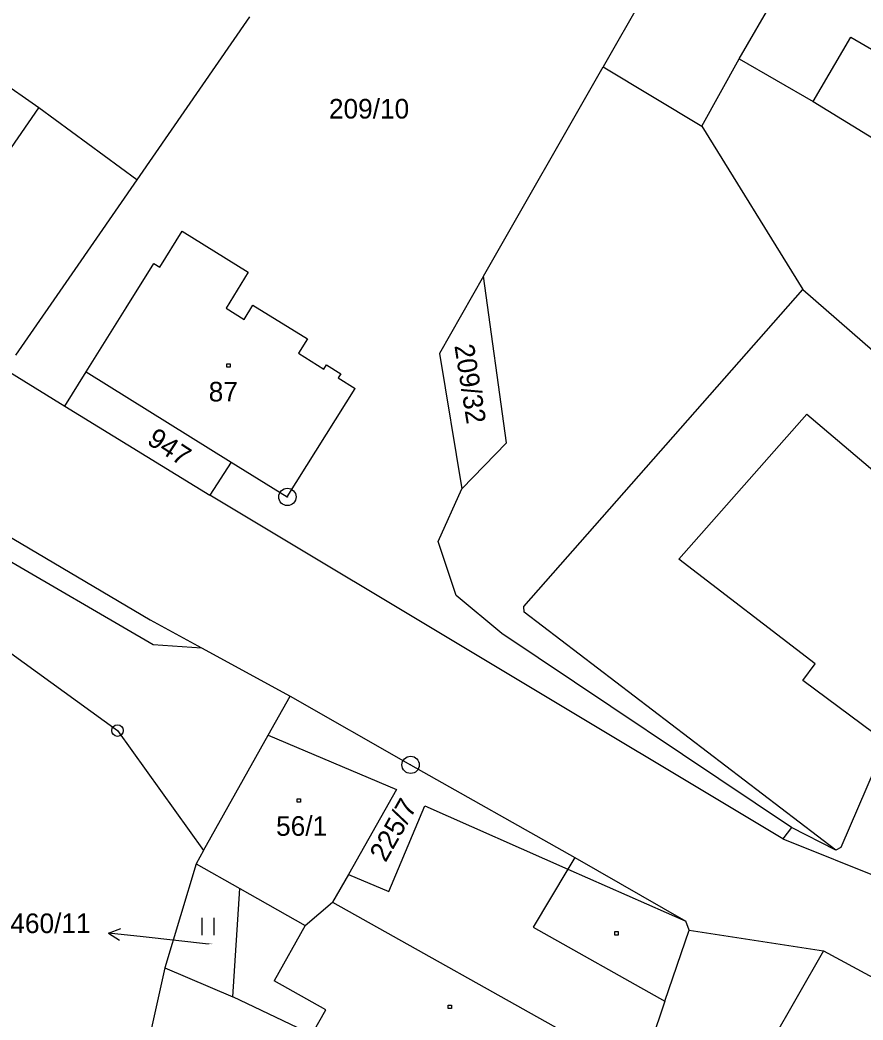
# Model space of a CAD drawing. Extents: x -796130 to -793145, y -1109506 to -1106267.
# Drawn here: x -794664.8 to -794591.8, y -1107676.5 to -1107589.9 of the extents above; entities that cross this region are included whole.
import ezdxf

# ---------------------------------------------------------------- set-up
doc = ezdxf.new("R2010")
doc.units = 0
for name, color, linetype in [('Komunikace', 7, 'Continuous'), ('Vrstva 1', 7, 'Continuous'), ('Vrstva 14', 7, 'Continuous'), ('Vrstva 15', 7, 'Continuous'), ('Vrstva 16', 7, 'Continuous'), ('Vrstva 2', 7, 'Continuous'), ('Vrstva 23', 7, 'Continuous'), ('Vrstva 25', 7, 'Continuous'), ('Vrstva 28', 7, 'Continuous')]:
    doc.layers.add(name, color=color, linetype=linetype)

msp = doc.modelspace()

# ---------------------------------------------------------------- linework, layer by layer
at = {"layer": 'Komunikace'}
msp.add_line((-794648.51, -1107669.95), (-794654.18, -1107669.32), dxfattribs=at)
at = {"layer": 'Vrstva 1'}
for p, q in [((-794605.66, -1107578.68), (-794614.29, -1107593.93)), ((-794644.96, -1107589.6), (-794654.73, -1107603.72)), ((-794624.67, -1107612.07), (-794614.29, -1107593.93)), ((-794614.29, -1107593.93), (-794605.74, -1107599.07)), ((-794605.74, -1107599.07), (-794602.51, -1107593.23)), ((-794602.51, -1107593.23), (-794596.1, -1107596.92)), ((-794596.1, -1107596.92), (-794590.11, -1107600.59)), ((-794667.79, -1107604.08), (-794663.22, -1107597.48)), ((-794654.73, -1107603.72), (-794663.22, -1107597.48)), ((-794605.74, -1107599.07), (-794596.99, -1107613.22)), ((-794654.73, -1107603.72), (-794660.1, -1107611.48)), ((-794652.74, -1107611.28), (-794650.79, -1107608.16)), ((-794650.79, -1107608.16), (-794645.06, -1107611.71)), ((-794655.65, -1107614.81), (-794653.25, -1107610.96)), ((-794653.25, -1107610.96), (-794652.74, -1107611.28)), ((-794660.1, -1107611.48), (-794665.24, -1107618.91)), ((-794645.06, -1107611.71), (-794646.98, -1107614.84)), ((-794624.67, -1107612.07), (-794628.49, -1107618.76)), ((-794622.69, -1107626.51), (-794624.67, -1107612.07)), ((-794596.99, -1107613.22), (-794570.24, -1107636.6)), ((-794645.43, -1107615.81), (-794644.66, -1107614.57)), ((-794644.66, -1107614.57), (-794639.94, -1107617.5)), ((-794659.11, -1107620.36), (-794655.65, -1107614.81)), ((-794646.98, -1107614.84), (-794645.43, -1107615.81)), ((-794639.94, -1107617.5), (-794640.71, -1107618.74)), ((-794640.71, -1107618.74), (-794638.51, -1107620.11)), ((-794628.49, -1107618.76), (-794626.55, -1107630.5)), ((-794638.51, -1107620.11), (-794638.28, -1107619.75)), ((-794638.28, -1107619.75), (-794637.05, -1107620.51)), ((-794666.1, -1107620.16), (-794660.96, -1107623.34)), ((-794660.96, -1107623.34), (-794659.11, -1107620.36)), ((-794659.11, -1107620.36), (-794646.53, -1107628.17)), ((-794637.05, -1107620.51), (-794637.28, -1107620.88)), ((-794637.28, -1107620.88), (-794635.79, -1107621.8)), ((-794641.68, -1107631.18), (-794635.79, -1107621.8)), ((-794660.96, -1107623.34), (-794648.39, -1107631.04)), ((-794626.55, -1107630.5), (-794622.69, -1107626.51)), ((-794646.53, -1107628.17), (-794648.39, -1107631.04)), ((-794646.53, -1107628.17), (-794641.68, -1107631.18)), ((-794673.06, -1107630.3), (-794653.57, -1107641.84)), ((-794598.74, -1107660.82), (-794648.39, -1107631.04)), ((-794628.61, -1107635.05), (-794626.55, -1107630.5)), ((-794673.39, -1107632.3), (-794653.29, -1107643.99)), ((-794627.03, -1107639.73), (-794628.61, -1107635.05)), ((-794623.1, -1107643.03), (-794627.03, -1107639.73)), ((-794653.57, -1107641.84), (-794649.11, -1107644.27)), ((-794668.13, -1107642.93), (-794656.4, -1107651.44)), ((-794597.97, -1107659.83), (-794623.1, -1107643.03)), ((-794653.29, -1107643.99), (-794649.11, -1107644.27)), ((-794649.11, -1107644.27), (-794641.42, -1107648.45)), ((-794643.33, -1107651.85), (-794641.42, -1107648.45)), ((-794641.42, -1107648.45), (-794630.99, -1107654.41)), ((-794656.4, -1107651.44), (-794648.93, -1107661.82)), ((-794648.93, -1107661.82), (-794643.33, -1107651.85)), ((-794643.33, -1107651.85), (-794632.21, -1107656.56)), ((-794630.99, -1107654.41), (-794616.76, -1107662.45)), ((-794590.74, -1107654.68), (-794593.72, -1107661.58)), ((-794632.21, -1107656.56), (-794636.38, -1107663.9)), ((-794632.87, -1107665.38), (-794629.75, -1107657.97)), ((-794629.75, -1107657.97), (-794617.36, -1107663.45)), ((-794597.97, -1107659.83), (-794598.74, -1107660.82)), ((-794594.15, -1107661.81), (-794597.97, -1107659.83)), ((-794598.74, -1107660.82), (-794581.21, -1107667.86)), ((-794593.72, -1107661.58), (-794594.15, -1107661.81)), ((-794648.93, -1107661.82), (-794649.59, -1107663)), ((-794616.76, -1107662.45), (-794607.15, -1107667.96)), ((-794649.59, -1107663), (-794652.3, -1107672)), ((-794649.59, -1107663), (-794645.8, -1107665.13)), ((-794636.38, -1107663.9), (-794637.76, -1107666.32)), ((-794636.38, -1107663.9), (-794632.87, -1107665.38)), ((-794617.36, -1107663.45), (-794607.15, -1107667.96)), ((-794646.4, -1107674.52), (-794645.8, -1107665.13)), ((-794645.8, -1107665.13), (-794640.13, -1107668.32)), ((-794640.13, -1107668.32), (-794637.76, -1107666.32)), ((-794606.85, -1107668.73), (-794607.15, -1107667.96)), ((-794608.97, -1107674.9), (-794606.85, -1107668.73)), ((-794606.85, -1107668.73), (-794595.21, -1107670.52)), ((-794595.21, -1107670.52), (-794600.01, -1107678.9)), ((-794595.21, -1107670.52), (-794585.56, -1107675.74)), ((-794652.3, -1107672), (-794659.77, -1107705.73)), ((-794652.3, -1107672), (-794646.4, -1107674.52)), ((-794639.55, -1107677.79), (-794646.4, -1107674.52)), ((-794608.97, -1107674.9), (-794611.1, -1107681.23))]:
    msp.add_line(p, q, dxfattribs=at)
at = {"layer": 'Vrstva 16'}
for p, q in [((-794657.161, -1107668.989), (-794656.112, -1107668.602)), ((-794654.18, -1107669.32), (-794657.161, -1107668.989)), ((-794657.161, -1107668.989), (-794656.222, -1107669.596))]:
    msp.add_line(p, q, dxfattribs=at)
at = {"layer": 'Vrstva 2'}
for p, q in [((-794602.51, -1107593.23), (-794597.06, -1107583.83)), ((-794596.1, -1107596.92), (-794592.83, -1107591.35)), ((-794592.83, -1107591.35), (-794574.52, -1107602.08)), ((-794663.22, -1107597.48), (-794668.67, -1107593.68)), ((-794621.18, -1107640.69), (-794596.99, -1107613.22)), ((-794607.75, -1107636.58), (-794596.64, -1107624.02)), ((-794596.64, -1107624.02), (-794575.12, -1107642.36)), ((-794595.92, -1107645.67), (-794607.75, -1107636.58)), ((-794621.15, -1107641.17), (-794621.18, -1107640.69)), ((-794594.15, -1107661.81), (-794621.15, -1107641.17)), ((-794596.99, -1107647.11), (-794595.92, -1107645.67)), ((-794589.79, -1107652.47), (-794596.99, -1107647.11)), ((-794616.76, -1107662.45), (-794617.36, -1107663.45)), ((-794617.36, -1107663.45), (-794620.38, -1107668.49)), ((-794637.76, -1107666.32), (-794611.1, -1107681.23)), ((-794640.13, -1107668.32), (-794642.81, -1107673.14)), ((-794620.38, -1107668.49), (-794608.97, -1107674.9)), ((-794638.35, -1107675.63), (-794642.81, -1107673.14)), ((-794639.55, -1107677.79), (-794638.35, -1107675.63))]:
    msp.add_line(p, q, dxfattribs=at)
at = {"layer": 'Vrstva 23'}
for p, q in [((-794649.05, -1107669.18), (-794649.05, -1107667.68)), ((-794648.05, -1107667.68), (-794648.05, -1107669.18))]:
    msp.add_line(p, q, dxfattribs=at)
at = {"layer": 'Vrstva 25'}
for p, q in [((-794646.93, -1107619.66), (-794646.63, -1107619.66)), ((-794646.93, -1107619.96), (-794646.93, -1107619.66)), ((-794646.63, -1107619.96), (-794646.93, -1107619.96)), ((-794646.63, -1107619.66), (-794646.63, -1107619.96)), ((-794640.83, -1107657.35), (-794640.53, -1107657.35)), ((-794640.83, -1107657.65), (-794640.83, -1107657.35)), ((-794640.53, -1107657.65), (-794640.83, -1107657.65)), ((-794640.53, -1107657.35), (-794640.53, -1107657.65)), ((-794613.29, -1107668.86), (-794612.99, -1107668.86)), ((-794613.29, -1107669.16), (-794613.29, -1107668.86)), ((-794612.99, -1107669.16), (-794613.29, -1107669.16)), ((-794612.99, -1107668.86), (-794612.99, -1107669.16)), ((-794627.74, -1107675.24), (-794627.44, -1107675.24)), ((-794627.74, -1107675.54), (-794627.74, -1107675.24)), ((-794627.44, -1107675.24), (-794627.44, -1107675.54)), ((-794627.44, -1107675.54), (-794627.74, -1107675.54))]:
    msp.add_line(p, q, dxfattribs=at)
at = {"layer": 'Vrstva 28'}
for centre, radius in [((-794641.67, -1107631.19), 0.75), ((-794641.67, -1107631.19), 0.01), ((-794656.4, -1107651.44), 0.5), ((-794656.4, -1107651.44), 0.01), ((-794630.99, -1107654.41), 0.75), ((-794630.99, -1107654.41), 0.01)]:
    msp.add_circle(centre, radius, dxfattribs=at)

# ---------------------------------------------------------------- texts
at = {"layer": 'Vrstva 14'}
for s, height, p in [('209/10', 1.7, (-794638.07, -1107598.4)), ('460/11', 0.1, (-794648.51, -1107669.95))]:
    msp.add_text(s, height=height, dxfattribs=at).set_placement(p)
for s, rotation, p in [('209/32', 279, (-794627.203, -1107618.082)), ('947', 326.8152, (-794653.94, -1107626.53)), ('225/7', 60.61014, (-794633.16, -1107662.93))]:
    msp.add_text(s, height=1.7, rotation=rotation, dxfattribs=at).set_placement(p)
at = {"layer": 'Vrstva 15'}
for s, p in [('87', (-794648.49, -1107622.92)), ('56/1', (-794642.65, -1107660.56))]:
    msp.add_text(s, height=1.7, dxfattribs=at).set_placement(p)
at = {"layer": 'Vrstva 16'}
msp.add_text('460/11', height=1.7, dxfattribs=at).set_placement((-794665.683, -1107668.99))

doc.saveas('drawing.dxf')
